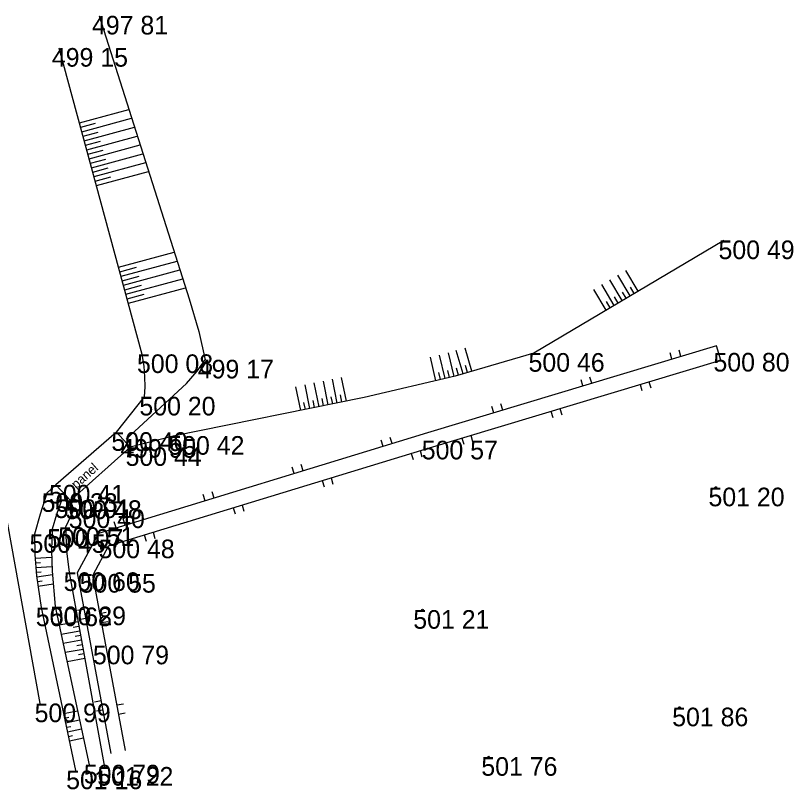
# Model space of a CAD drawing. Extents: x -554123 to -553118, y -1076825 to -1073672.
# Drawn here: x -553426.8 to -553384.99, y -1076810.79 to -1076769.22 of the extents above; entities that cross this region are included whole.
import ezdxf

# ---------------------------------------------------------------- set-up
doc = ezdxf.new("R2010")
doc.units = 0
for name, color, linetype in [('1', 7, 'Continuous'), ('12', 7, 'Continuous'), ('17', 7, 'Continuous'), ('18', 7, 'Continuous'), ('26', 7, 'Continuous'), ('27', 7, 'Continuous'), ('52', 7, 'Continuous'), ('6', 7, 'Continuous')]:
    doc.layers.add(name, color=color, linetype=linetype)

# ---------------------------------------------------------------- blocks, each defined once
blk = doc.blocks.new('POINT_DISPLAY')
blk.add_line((0, 0), (0, 0))
blk = doc.blocks.new('T')
at = {"layer": '6'}
blk.add_circle((0, 0), 0.05, dxfattribs=at)

msp = doc.modelspace()

# ---------------------------------------------------------------- linework, layer by layer
at = {"layer": '12'}
for p, q in [((-553389.125, -1076786.956), (-553404.651, -1076791.63)), ((-553388.894, -1076787.723), (-553389.125, -1076786.956)), ((-553391.519, -1076787.677), (-553391.62, -1076787.342)), ((-553391.04, -1076787.533), (-553391.141, -1076787.197)), ((-553404.728, -1076792.489), (-553388.894, -1076787.723)), ((-553396.307, -1076789.118), (-553396.408, -1076788.783)), ((-553395.828, -1076788.974), (-553395.929, -1076788.639)), ((-553393.237, -1076789.03), (-553393.136, -1076789.365)), ((-553392.758, -1076788.886), (-553392.658, -1076789.221)), ((-553401.094, -1076790.559), (-553401.195, -1076790.224)), ((-553400.616, -1076790.415), (-553400.717, -1076790.08)), ((-553398.025, -1076790.471), (-553397.924, -1076790.807)), ((-553397.546, -1076790.327), (-553397.445, -1076790.662)), ((-553404.651, -1076791.63), (-553422.343, -1076797.035)), ((-553406.564, -1076792.214), (-553406.666, -1076791.88)), ((-553402.813, -1076791.913), (-553402.712, -1076792.248)), ((-553402.334, -1076791.768), (-553402.233, -1076792.104)), ((-553407.042, -1076792.36), (-553407.144, -1076792.026)), ((-553421.796, -1076797.704), (-553404.728, -1076792.489)), ((-553405.538, -1076792.736), (-553405.436, -1076793.071)), ((-553405.06, -1076792.59), (-553404.958, -1076792.925)), ((-553411.824, -1076793.821), (-553411.926, -1076793.487)), ((-553411.346, -1076793.675), (-553411.448, -1076793.34)), ((-553409.842, -1076794.051), (-553409.739, -1076794.386)), ((-553410.32, -1076794.198), (-553410.217, -1076794.532)), ((-553416.127, -1076795.136), (-553416.23, -1076794.801)), ((-553416.606, -1076795.282), (-553416.708, -1076794.947)), ((-553415.102, -1076795.659), (-553414.999, -1076795.993)), ((-553414.623, -1076795.512), (-553414.521, -1076795.847)), ((-553421.387, -1076796.743), (-553421.49, -1076796.408)), ((-553420.909, -1076796.597), (-553421.011, -1076796.262)), ((-553419.405, -1076796.973), (-553419.303, -1076797.308)), ((-553422.343, -1076797.035), (-553423.489, -1076799.155)), ((-553419.883, -1076797.12), (-553419.781, -1076797.454)), ((-553421.796, -1076797.704), (-553422.65, -1076799.284)), ((-553423.489, -1076799.155), (-553421.675, -1076808.856)), ((-553420.888, -1076808.709), (-553422.65, -1076799.284)), ((-553423.121, -1076801.121), (-553423.465, -1076801.185)), ((-553422.266, -1076801.337), (-553421.922, -1076801.272)), ((-553423.029, -1076801.612), (-553423.374, -1076801.677)), ((-553422.174, -1076801.828), (-553421.83, -1076801.764)), ((-553422.202, -1076806.036), (-553422.546, -1076806.1)), ((-553421.347, -1076806.252), (-553421.003, -1076806.187)), ((-553422.11, -1076806.527), (-553422.454, -1076806.592)), ((-553421.256, -1076806.743), (-553420.911, -1076806.679))]:
    msp.add_line(p, q, dxfattribs=at)
at = {"layer": '17'}
msp.add_line((-553425.47, -1076806.18), (-553431.22, -1076774.44), dxfattribs=at)
at = {"layer": '18'}
for p, q in [((-553421.38, -1076791.6), (-553424.63, -1076794.43)), ((-553420.63, -1076792.41), (-553421.38, -1076791.6)), ((-553423.84, -1076795.27), (-553420.63, -1076792.41)), ((-553424.63, -1076794.43), (-553423.84, -1076795.27)), ((-553423.84, -1076795.27), (-553423.84, -1076795.26))]:
    msp.add_line(p, q, dxfattribs=at)
at = {"layer": '26'}
for p, q in [((-553423.362, -1076774.975), (-553420.71, -1076774.256)), ((-553423.231, -1076775.457), (-553420.559, -1076774.733)), ((-553423.297, -1076775.216), (-553422.498, -1076775)), ((-553423.101, -1076775.94), (-553420.407, -1076775.21)), ((-553423.166, -1076775.699), (-553422.361, -1076775.481)), ((-553423.035, -1076776.181), (-553422.224, -1076775.961)), ((-553422.97, -1076776.423), (-553420.255, -1076775.687)), ((-553422.904, -1076776.664), (-553422.087, -1076776.442)), ((-553422.839, -1076776.905), (-553420.103, -1076776.164)), ((-553422.774, -1076777.146), (-553421.95, -1076776.923)), ((-553422.708, -1076777.388), (-553419.951, -1076776.641)), ((-553422.578, -1076777.87), (-553419.8, -1076777.117)), ((-553422.643, -1076777.629), (-553421.813, -1076777.404)), ((-553422.447, -1076778.353), (-553419.648, -1076777.595)), ((-553422.512, -1076778.112), (-553421.676, -1076777.885)), ((-553421.258, -1076782.739), (-553418.268, -1076781.929)), ((-553421.193, -1076782.98), (-553420.293, -1076782.736)), ((-553421.128, -1076783.221), (-553418.117, -1076782.405)), ((-553420.997, -1076783.704), (-553417.965, -1076782.882)), ((-553393.766, -1076784.278), (-553394.429, -1076783.16)), ((-553393.336, -1076784.024), (-553393.999, -1076782.905)), ((-553421.062, -1076783.463), (-553420.156, -1076783.217)), ((-553420.866, -1076784.187), (-553417.813, -1076783.36)), ((-553394.197, -1076784.533), (-553394.86, -1076783.415)), ((-553420.932, -1076783.945), (-553420.019, -1076783.698)), ((-553420.735, -1076784.669), (-553417.661, -1076783.836)), ((-553395.057, -1076785.043), (-553395.72, -1076783.925)), ((-553394.627, -1076784.788), (-553395.29, -1076783.67)), ((-553393.551, -1076784.151), (-553393.75, -1076783.815)), ((-553420.801, -1076784.428), (-553419.882, -1076784.179)), ((-553394.412, -1076784.661), (-553394.611, -1076784.325)), ((-553393.982, -1076784.406), (-553394.181, -1076784.071)), ((-553394.842, -1076784.916), (-553395.041, -1076784.58)), ((-553403.228, -1076788.605), (-553403.525, -1076787.339)), ((-553402.748, -1076788.466), (-553403.114, -1076787.219)), ((-553402.268, -1076788.325), (-553402.634, -1076787.078)), ((-553404.202, -1076788.833), (-553404.499, -1076787.568)), ((-553403.715, -1076788.719), (-553404.012, -1076787.454)), ((-553402.988, -1076788.537), (-553403.098, -1076788.163)), ((-553402.508, -1076788.396), (-553402.618, -1076788.022)), ((-553403.959, -1076788.776), (-553404.048, -1076788.397)), ((-553403.472, -1076788.662), (-553403.561, -1076788.282)), ((-553410.978, -1076790.329), (-553411.235, -1076789.055)), ((-553410.488, -1076790.23), (-553410.745, -1076788.956)), ((-553409.998, -1076790.131), (-553410.255, -1076788.857)), ((-553409.508, -1076790.032), (-553409.765, -1076788.758)), ((-553409.017, -1076789.933), (-553409.274, -1076788.659)), ((-553411.468, -1076790.428), (-553411.725, -1076789.154)), ((-553410.243, -1076790.181), (-553410.32, -1076789.798)), ((-553409.753, -1076790.082), (-553409.83, -1076789.7)), ((-553409.262, -1076789.983), (-553409.339, -1076789.601)), ((-553411.223, -1076790.378), (-553411.3, -1076789.996)), ((-553410.733, -1076790.279), (-553410.81, -1076789.897)), ((-553425.738, -1076798.375), (-553424.849, -1076798.307)), ((-553425.719, -1076798.624), (-553425.456, -1076798.604)), ((-553425.7, -1076798.874), (-553424.838, -1076798.808)), ((-553425.681, -1076799.123), (-553425.426, -1076799.103)), ((-553425.657, -1076799.372), (-553424.816, -1076799.251)), ((-553425.622, -1076799.619), (-553425.373, -1076799.583)), ((-553425.586, -1076799.867), (-553424.771, -1076799.75)), ((-553423.436, -1076801.793), (-553424.445, -1076801.976)), ((-553423.347, -1076802.285), (-553424.34, -1076802.465)), ((-553423.392, -1076802.039), (-553423.692, -1076802.094)), ((-553423.258, -1076802.777), (-553424.235, -1076802.954)), ((-553423.302, -1076802.531), (-553423.598, -1076802.585)), ((-553423.168, -1076803.269), (-553424.13, -1076803.444)), ((-553423.213, -1076803.023), (-553423.504, -1076803.076)), ((-553423.124, -1076803.515), (-553423.41, -1076803.567)), ((-553423.079, -1076803.761), (-553424.026, -1076803.933)), ((-553424.216, -1076806.722), (-553423.462, -1076806.563)), ((-553424.164, -1076806.967), (-553423.938, -1076806.919)), ((-553424.112, -1076807.212), (-553423.358, -1076807.053)), ((-553424.061, -1076807.456), (-553423.834, -1076807.408)), ((-553424.009, -1076807.701), (-553423.253, -1076807.541)), ((-553423.957, -1076807.945), (-553423.731, -1076807.897)), ((-553423.906, -1076808.19), (-553423.148, -1076808.03))]:
    msp.add_line(p, q, dxfattribs=at)
at = {"layer": '27'}
for p, q in [((-553419.99, -1076787.42), (-553424.45, -1076770.96)), ((-553388.74, -1076781.3), (-553398.95, -1076787.35)), ((-553421.38, -1076791.6), (-553419.86, -1076789.7)), ((-553418.32, -1076791.81), (-553420.63, -1076792.41)), ((-553425.12, -1076794.88), (-553424.63, -1076794.43)), ((-553423.67, -1076795.75), (-553423.84, -1076795.27)), ((-553423.67, -1076795.75), (-553424.12, -1076796.71)), ((-553423.92, -1076799.13), (-553422.02, -1076809.59)), ((-553425.42, -1076801.02), (-553423.57, -1076809.78)), ((-553424.66, -1076800.97), (-553422.84, -1076809.47))]:
    msp.add_line(p, q, dxfattribs=at)
for points in [[(-553422.31, -1076769.23), (-553417.472, -1076784.431), (-553416.942, -1076786.198), (-553416.61, -1076787.71)], [(-553398.95, -1076787.35), (-553403.175, -1076788.592), (-553408.064, -1076789.741), (-553418.32, -1076791.81)], [(-553420.86, -1076791.97), (-553417.616, -1076788.989), (-553417.042, -1076788.326), (-553416.61, -1076787.71)], [(-553419.86, -1076789.7), (-553419.829, -1076789.166), (-553419.84, -1076788.621), (-553419.888, -1076788.054), (-553419.99, -1076787.42)], [(-553425.12, -1076794.88), (-553425.481, -1076795.999), (-553425.78, -1076797.08)], [(-553424.31, -1076795.21), (-553424.59, -1076796.014), (-553424.82, -1076796.81)], [(-553424.82, -1076796.81), (-553424.856, -1076797.958), (-553424.833, -1076799.069), (-553424.66, -1076800.97)], [(-553424.12, -1076796.71), (-553424.05, -1076797.972), (-553423.92, -1076799.13)], [(-553425.78, -1076797.08), (-553425.754, -1076798.164), (-553425.666, -1076799.312), (-553425.42, -1076801.02)]]:
    msp.add_lwpolyline(points, dxfattribs=at)

# ---------------------------------------------------------------- block references
at = {"layer": '1'}
for p in [(-553422.31, -1076769.23), (-553424.45, -1076770.96), (-553388.74, -1076781.3), (-553398.95, -1076787.35), (-553389.01, -1076787.34), (-553419.99, -1076787.42), (-553416.61, -1076787.71), (-553419.86, -1076789.7), (-553421.38, -1076791.6), (-553420.86, -1076791.97), (-553418.32, -1076791.81), (-553404.69, -1076792.06), (-553420.63, -1076792.41), (-553424.63, -1076794.43), (-553425.12, -1076794.88), (-553389.17, -1076794.58), (-553424.31, -1076795.21), (-553423.84, -1076795.26), (-553423.84, -1076795.27), (-553423.67, -1076795.75), (-553424.82, -1076796.81), (-553424.12, -1076796.71), (-553425.78, -1076797.08), (-553422.07, -1076797.37), (-553423.92, -1076799.13), (-553423.07, -1076799.22), (-553425.42, -1076801.02), (-553424.66, -1076800.97), (-553404.93, -1076801.16), (-553422.35, -1076803.07), (-553425.47, -1076806.18), (-553391.11, -1076806.4), (-553401.37, -1076809.06), (-553422.84, -1076809.47), (-553423.57, -1076809.78), (-553422.02, -1076809.59)]:
    msp.add_blockref('POINT_DISPLAY', p, dxfattribs=at)
at = {"layer": '6'}
for p in [(-553389.17, -1076794.58), (-553404.93, -1076801.16), (-553391.11, -1076806.4), (-553401.37, -1076809.06)]:
    msp.add_blockref('T', p, dxfattribs=at)

# ---------------------------------------------------------------- texts
at = {"layer": '52'}
msp.add_text('panel', height=0.5, rotation=41.6999, dxfattribs=at).set_placement((-553423.533, -1076794.672))
at = {"layer": '6'}
for s, p in [('497 81 ', (-553422.689, -1076770.23)), ('499 15 ', (-553424.845, -1076771.96)), ('500 49 ', (-553389.018, -1076782.3)), ('500 46 ', (-553399.228, -1076788.35)), ('500 80 ', (-553389.29, -1076788.34)), ('500 08 ', (-553420.27, -1076788.42)), ('499 17 ', (-553417.003, -1076788.71)), ('500 20 ', (-553420.14, -1076790.7)), ('500 40 ', (-553421.648, -1076792.6)), ('499 95 ', (-553421.158, -1076792.97)), ('500 42 ', (-553418.586, -1076792.81)), ('500 44 ', (-553420.884, -1076793.41)), ('500 57 ', (-553404.966, -1076793.06)), ('500 41 ', (-553425.003, -1076795.43)), ('500 33 ', (-553425.398, -1076795.88)), ('501 20 ', (-553389.557, -1076795.58)), ('500 01 ', (-553424.697, -1076796.21)), ('500 48 ', (-553424.106, -1076796.26)), ('500 48 ', (-553424.106, -1076796.27)), ('500 40 ', (-553423.938, -1076796.75)), ('500 07 ', (-553425.098, -1076797.81)), ('500 51 ', (-553424.505, -1076797.71)), ('500 45 ', (-553426.046, -1076798.08)), ('500 48 ', (-553422.336, -1076798.37)), ('500 60 ', (-553424.212, -1076800.13)), ('500 55 ', (-553423.348, -1076800.22)), ('500 68 ', (-553425.71, -1076802.02)), ('500 29 ', (-553424.95, -1076801.97)), ('501 21 ', (-553405.422, -1076802.16)), ('500 79 ', (-553422.638, -1076804.07)), ('500 99 ', (-553425.772, -1076807.18)), ('501 86 ', (-553391.507, -1076807.4)), ('501 76 ', (-553401.765, -1076810.06)), ('500 79 ', (-553423.128, -1076810.47)), ('501 16 ', (-553424.076, -1076810.78)), ('501 22 ', (-553422.405, -1076810.59))]:
    msp.add_text(s, height=1, dxfattribs=at).set_placement(p)

doc.saveas('drawing.dxf')
